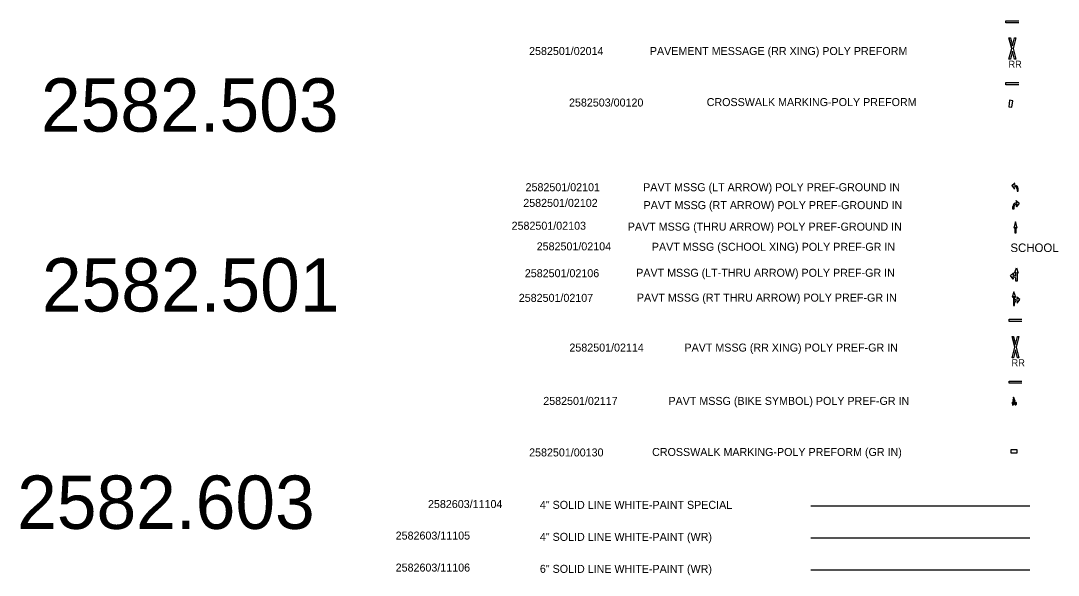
# Model space of a CAD drawing. Extents: x 2147716 to 2176321, y 2125040 to 2131750.
# Drawn here: x 2155849 to 2156821, y 2126811 to 2127331 of the extents above; entities that cross this region are included whole.
import ezdxf

# ---------------------------------------------------------------- set-up
doc = ezdxf.new("R2010")
doc.units = 0
for name, color, linetype in [('DETAIL TXT', 7, 'Continuous'), ('PVMT MARK', 7, 'Continuous'), ('PVMT STRP', 7, 'Continuous')]:
    doc.layers.add(name, color=color, linetype=linetype)

msp = doc.modelspace()

# ---------------------------------------------------------------- linework, layer by layer
at = {"layer": 'PVMT MARK'}
for p, q in [((2156771.9, 2127330.76), (2156783.9, 2127330.76)), ((2156771.9, 2127328.76), (2156771.9, 2127330.76)), ((2156783.9, 2127328.76), (2156771.9, 2127328.76)), ((2156774.7, 2127314.76), (2156777.3, 2127304.76)), ((2156777.3, 2127304.76), (2156774.7, 2127314.76)), ((2156777.3, 2127304.76), (2156774.7, 2127314.76)), ((2156774.7, 2127314.76), (2156776, 2127314.76)), ((2156776, 2127314.76), (2156777.9, 2127307.26)), ((2156777.9, 2127307.26), (2156779.9, 2127314.76)), ((2156781.2, 2127314.76), (2156778.6, 2127304.76)), ((2156779.9, 2127314.76), (2156781.2, 2127314.76)), ((2156774.7, 2127294.76), (2156777.3, 2127304.76)), ((2156777.9, 2127302.26), (2156776, 2127294.76)), ((2156777.9, 2127304.76), (2156777.9, 2127304.76)), ((2156779.9, 2127294.76), (2156777.9, 2127302.26)), ((2156778.6, 2127304.76), (2156781.2, 2127294.76)), ((2156776, 2127294.76), (2156774.7, 2127294.76)), ((2156781.2, 2127294.76), (2156779.9, 2127294.76)), ((2156771.9, 2127272.76), (2156783.9, 2127272.76)), ((2156771.9, 2127270.76), (2156771.9, 2127272.76)), ((2156783.9, 2127270.76), (2156771.9, 2127270.76)), ((2156780.27, 2127178.92), (2156777.29, 2127176.44)), ((2156777.29, 2127176.44), (2156779.77, 2127172.97)), ((2156779.37, 2127176.64), (2156780.27, 2127178.92)), ((2156780.03, 2127176.64), (2156779.37, 2127176.64)), ((2156779.77, 2127172.97), (2156779.37, 2127175.09)), ((2156779.37, 2127175.09), (2156780.03, 2127175.09)), ((2156782.25, 2127172.97), (2156782.25, 2127170.99)), ((2156782.25, 2127170.99), (2156783.25, 2127170.99)), ((2156783.25, 2127170.99), (2156783.25, 2127173.47)), ((2156778.39, 2127154.19), (2156778.39, 2127156.67)), ((2156779.38, 2127156.17), (2156779.38, 2127154.19)), ((2156782.27, 2127159.84), (2156781.36, 2127162.12)), ((2156781.36, 2127162.12), (2156784.34, 2127159.64)), ((2156781.61, 2127159.84), (2156782.27, 2127159.84)), ((2156782.27, 2127158.29), (2156781.61, 2127158.29)), ((2156784.34, 2127159.64), (2156781.86, 2127156.17)), ((2156781.86, 2127156.17), (2156782.27, 2127158.29)), ((2156779.38, 2127154.19), (2156778.39, 2127154.19)), ((2156779.2, 2127136.19), (2156780.32, 2127137.31)), ((2156780.32, 2127137.31), (2156780.32, 2127131.86)), ((2156781.31, 2127131.86), (2156781.31, 2127137.31)), ((2156781.31, 2127137.31), (2156782.44, 2127136.24)), ((2156780.32, 2127131.86), (2156781.31, 2127131.86)), ((2156780, 2127094.13), (2156781.74, 2127099.09)), ((2156781.74, 2127099.09), (2156783.47, 2127094.13)), ((2156776.28, 2127091.98), (2156779.02, 2127094.3)), ((2156778.76, 2127088.51), (2156776.28, 2127091.98)), ((2156779.02, 2127094.3), (2156778.36, 2127092.23)), ((2156778.36, 2127092.23), (2156779.02, 2127092.23)), ((2156779.09, 2127090.66), (2156778.43, 2127090.66)), ((2156778.43, 2127090.66), (2156778.76, 2127088.51)), ((2156781.24, 2127095.12), (2156780, 2127094.13)), ((2156781.24, 2127091.15), (2156781.24, 2127095.12)), ((2156781.24, 2127086.52), (2156781.24, 2127088.51)), ((2156783.47, 2127094.13), (2156782.23, 2127095.12)), ((2156782.23, 2127095.12), (2156782.23, 2127086.52)), ((2156782.23, 2127086.52), (2156781.24, 2127086.52)), ((2156779.32, 2127076.46), (2156777.58, 2127071.5)), ((2156777.58, 2127071.5), (2156778.82, 2127072.49)), ((2156778.82, 2127072.49), (2156778.82, 2127063.89)), ((2156781.06, 2127071.5), (2156779.32, 2127076.46)), ((2156779.82, 2127068.52), (2156779.82, 2127072.49)), ((2156779.82, 2127072.49), (2156781.06, 2127071.5)), ((2156781.97, 2127068.02), (2156782.63, 2127068.02)), ((2156784.78, 2127069.35), (2156782.03, 2127071.66)), ((2156782.03, 2127071.66), (2156782.69, 2127069.6)), ((2156782.69, 2127069.6), (2156782.03, 2127069.6)), ((2156782.3, 2127065.87), (2156784.78, 2127069.35)), ((2156782.63, 2127068.02), (2156782.3, 2127065.87)), ((2156778.82, 2127063.89), (2156779.82, 2127063.89)), ((2156779.82, 2127063.89), (2156779.82, 2127065.87)), ((2156774.76, 2127050.84), (2156786.76, 2127050.84)), ((2156774.76, 2127048.84), (2156774.76, 2127050.84)), ((2156786.76, 2127048.84), (2156774.76, 2127048.84)), ((2156777.56, 2127034.84), (2156780.16, 2127024.84)), ((2156780.16, 2127024.84), (2156777.56, 2127034.84)), ((2156780.16, 2127024.84), (2156777.56, 2127034.84)), ((2156777.56, 2127034.84), (2156778.86, 2127034.84)), ((2156778.86, 2127034.84), (2156780.76, 2127027.34)), ((2156780.76, 2127027.34), (2156782.76, 2127034.84)), ((2156784.06, 2127034.84), (2156781.46, 2127024.84)), ((2156782.76, 2127034.84), (2156784.06, 2127034.84)), ((2156777.56, 2127014.84), (2156780.16, 2127024.84)), ((2156780.76, 2127022.34), (2156778.86, 2127014.84)), ((2156780.76, 2127024.84), (2156780.76, 2127024.84)), ((2156782.76, 2127014.84), (2156780.76, 2127022.34)), ((2156781.46, 2127024.84), (2156784.06, 2127014.84)), ((2156778.86, 2127014.84), (2156777.56, 2127014.84)), ((2156784.06, 2127014.84), (2156782.76, 2127014.84)), ((2156774.76, 2126992.84), (2156786.76, 2126992.84)), ((2156774.76, 2126990.84), (2156774.76, 2126992.84)), ((2156786.76, 2126990.84), (2156774.76, 2126990.84)), ((2156777.81, 2126972.83), (2156777.81, 2126972.93)), ((2156778.91, 2126976.63), (2156778.41, 2126975.13)), ((2156778.41, 2126975.13), (2156778.61, 2126974.53)), ((2156778.58, 2126977.41), (2156778.72, 2126977.42)), ((2156778.61, 2126974.53), (2156779.11, 2126975.93)), ((2156779.81, 2126974.63), (2156778.71, 2126973.93)), ((2156778.71, 2126973.93), (2156779.41, 2126973.03)), ((2156779.41, 2126977.13), (2156778.91, 2126976.63)), ((2156779.11, 2126975.93), (2156779.81, 2126974.63)), ((2156779.19, 2126977.42), (2156779.34, 2126977.41)), ((2156780.61, 2126974.13), (2156779.41, 2126977.13)), ((2156779.41, 2126973.73), (2156780.01, 2126974.23)), ((2156779.61, 2126973.33), (2156779.41, 2126973.73)), ((2156779.41, 2126973.03), (2156779.61, 2126973.33)), ((2156780.01, 2126974.23), (2156779.51, 2126972.03)), ((2156779.51, 2126972.03), (2156779.61, 2126971.33)), ((2156779.61, 2126971.43), (2156780.61, 2126974.13)), ((2156780.31, 2126971.03), (2156780.81, 2126971.13))]:
    msp.add_line(p, q, dxfattribs=at)
for points in [[(2156774.51, 2127250.2), (2156777.48, 2127249.83), (2156778.23, 2127255.78), (2156775.25, 2127256.15)], [(2156782.38, 2126925.57), (2156782.38, 2126928.57), (2156776.38, 2126928.57), (2156776.38, 2126925.57)]]:
    msp.add_lwpolyline(points, close=True, dxfattribs=at)
msp.add_lwpolyline([(2156782.44, 2127136.24), (2156780.82, 2127142.32), (2156779.2, 2127136.24)], dxfattribs=at)
for centre, radius in [((2156777.9, 2127304.76), 0.04), ((2156777.9, 2127304.76), 0.035), ((2156780.76, 2127024.84), 0.04), ((2156780.76, 2127024.84), 0.035)]:
    msp.add_circle(centre, radius, dxfattribs=at)
for centre, radius, start, end in [((2156780.02, 2127173.42), 3.22, 0.85489, 89.91229), ((2156780.1, 2127172.94), 2.15, 0.74176, 90.20562), ((2156781.61, 2127156.62), 3.22, 90.08771, 179.14511), ((2156781.53, 2127156.14), 2.15, 89.79438, 179.25824), ((2156778.83, 2127089.01), 3.23, 41.67105, 86.55067), ((2156779.09, 2127088.51), 2.15, 0, 90), ((2156782.22, 2127066.38), 3.23, 93.44933, 138.32895), ((2156781.97, 2127065.87), 2.15, 90, 180), ((2156778.96, 2126977.41), 0.38, 0, 180), ((2156778.96, 2126977.42), 0.233, 179.88048, 0.11957)]:
    msp.add_arc(centre, radius, start, end, dxfattribs=at)
for centre, major_axis, ratio, start_param, end_param in [((2156778.35, 2126971.84), (0.02, -1.55), 0.456256, 3.992611, 7.057282), ((2156778.35, 2126971.84), (0.02, -1.55), 0.456256, 0.776758, 3.974471), ((2156778.35, 2126971.82), (0.01, -1.05), 0.197843, 4.125672, 6.670705), ((2156778.35, 2126971.82), (0.01, -1.05), 0.197843, 0.431648, 4.124808), ((2156780.91, 2126971.82), (0.02, -1.55), 0.456256, 5.23952, 11.521386), ((2156780.91, 2126971.82), (0.01, -1.05), 0.197843, 5.45221, 11.728621)]:
    msp.add_ellipse(centre, major_axis=major_axis, ratio=ratio, start_param=start_param, end_param=end_param, dxfattribs=at)
at = {"layer": 'PVMT STRP'}
for p, q in [((2156589.06, 2126876.07), (2156794.27, 2126876.07)), ((2156589.06, 2126846.07), (2156794.27, 2126846.07)), ((2156589.06, 2126816.07), (2156794.27, 2126816.07))]:
    msp.add_line(p, q, dxfattribs=at)

# ---------------------------------------------------------------- texts
at = {"layer": 'DETAIL TXT'}
for s, height, p in [('2582501/02014', 7.5, (2156324.94, 2127298.63)), ('PAVEMENT MESSAGE (RR XING) POLY PREFORM', 7.5, (2156438.14, 2127298.63)), ('2582.503', 50, (2155867.47, 2127226.78)), ('2582503/00120', 7.5, (2156362.36, 2127250.33)), ('CROSSWALK MARKING-POLY PREFORM', 7.5, (2156491.42, 2127250.75)), ('2582501/02101', 7.5, (2156321.65, 2127170.95)), ('PAVT MSSG (LT ARROW) POLY PREF-GROUND IN', 7.5, (2156431.85, 2127170.95)), ('2582501/02102', 7.5, (2156319.5, 2127156.25)), ('PAVT MSSG (RT ARROW) POLY PREF-GROUND IN', 7.5, (2156432.27, 2127154.15)), ('2582501/02103', 7.5, (2156308.57, 2127134.83)), ('PAVT MSSG (THRU ARROW) POLY PREF-GROUND IN', 7.5, (2156417.42, 2127133.99)), ('2582501/02104', 7.5, (2156332.08, 2127115.51)), ('PAVT MSSG (SCHOOL XING) POLY PREF-GR IN', 7.5, (2156440.01, 2127115.09)), ('2582.501', 50, (2155868.37, 2127058.14)), ('2582501/02106', 7.5, (2156320.95, 2127090.31)), ('PAVT MSSG (LT-THRU ARROW) POLY PREF-GR IN', 7.5, (2156425.37, 2127090.73)), ('2582501/02107', 7.5, (2156315.29, 2127067.21)), ('PAVT MSSG (RT THRU ARROW) POLY PREF-GR IN', 7.5, (2156426, 2127067.42)), ('2582501/02114', 7.5, (2156362.74, 2127020.59)), ('PAVT MSSG (RR XING) POLY PREF-GR IN', 7.5, (2156470.55, 2127020.59)), ('2582501/02117', 7.5, (2156338.22, 2126970.59)), ('PAVT MSSG (BIKE SYMBOL) POLY PREF-GR IN', 7.5, (2156455.55, 2126970.59)), ('2582501/00130', 7.5, (2156324.98, 2126922.29)), ('CROSSWALK MARKING-POLY PREFORM (GR IN)', 7.5, (2156440.25, 2126922.71)), ('2582.603', 50, (2155845.16, 2126854.35)), ('2582603/11104', 7.5, (2156230.21, 2126873.9)), ('4" SOLID LINE WHITE-PAINT SPECIAL', 7.5, (2156335.07, 2126873.14)), ('2582603/11105', 7.5, (2156199.92, 2126844.34)), ('4" SOLID LINE WHITE-PAINT (WR)', 7.5, (2156335.07, 2126843.14)), ('2582603/11106', 7.5, (2156199.92, 2126814.34)), ('6" SOLID LINE WHITE-PAINT (WR)', 7.5, (2156335.07, 2126813.14))]:
    msp.add_text(s, height=height, dxfattribs=at).set_placement(p)
at = {"layer": 'PVMT MARK'}
for s, height, p in [('RR', 6.5, (2156774.2, 2127286.76)), ("AREA = 15 SQ'", 0.0992, (2156780.08, 2127176.01)), ("REM = 48 SQ '", 0.0992, (2156780.13, 2127175.68)), ("PERIMETER = 30 '", 0.0992, (2156780.15, 2127175.36)), ('PERIMETER 30 FT', 0.0907, (2156780.06, 2127137.96)), ('REM 35 SF', 0.0907, (2156780.3, 2127138.3)), ('AREA 15 SF', 0.0907, (2156780.39, 2127138.6)), ('SCHOOL', 8, (2156776.07, 2127113.91)), ('AREA 26 SQ FT', 0.0992, (2156777.52, 2127091.8)), ('REM 95 SQ FT', 0.0992, (2156777.54, 2127091.59)), ('PERIMETER 50FT', 0.0992, (2156777.57, 2127091.35)), ('RR', 6.5, (2156777.06, 2127006.84))]:
    msp.add_text(s, height=height, dxfattribs=at).set_placement(p)
for s, p in [("PERIMETER = 30 '", (2156780.13, 2127158.49)), ("REM = 48 SQ '", (2156780.39, 2127158.81)), ("AREA = 15 SQ'", (2156780.49, 2127159.14)), ('PERIMETER 50FT', (2156782.23, 2127068.72)), ('AREA 26 SQ FT', (2156782.34, 2127069.17)), ('REM 95 SQ FT', (2156782.4, 2127068.96))]:
    msp.add_text(s, height=0.0992, rotation=360, dxfattribs=at).set_placement(p)

doc.saveas('drawing.dxf')
